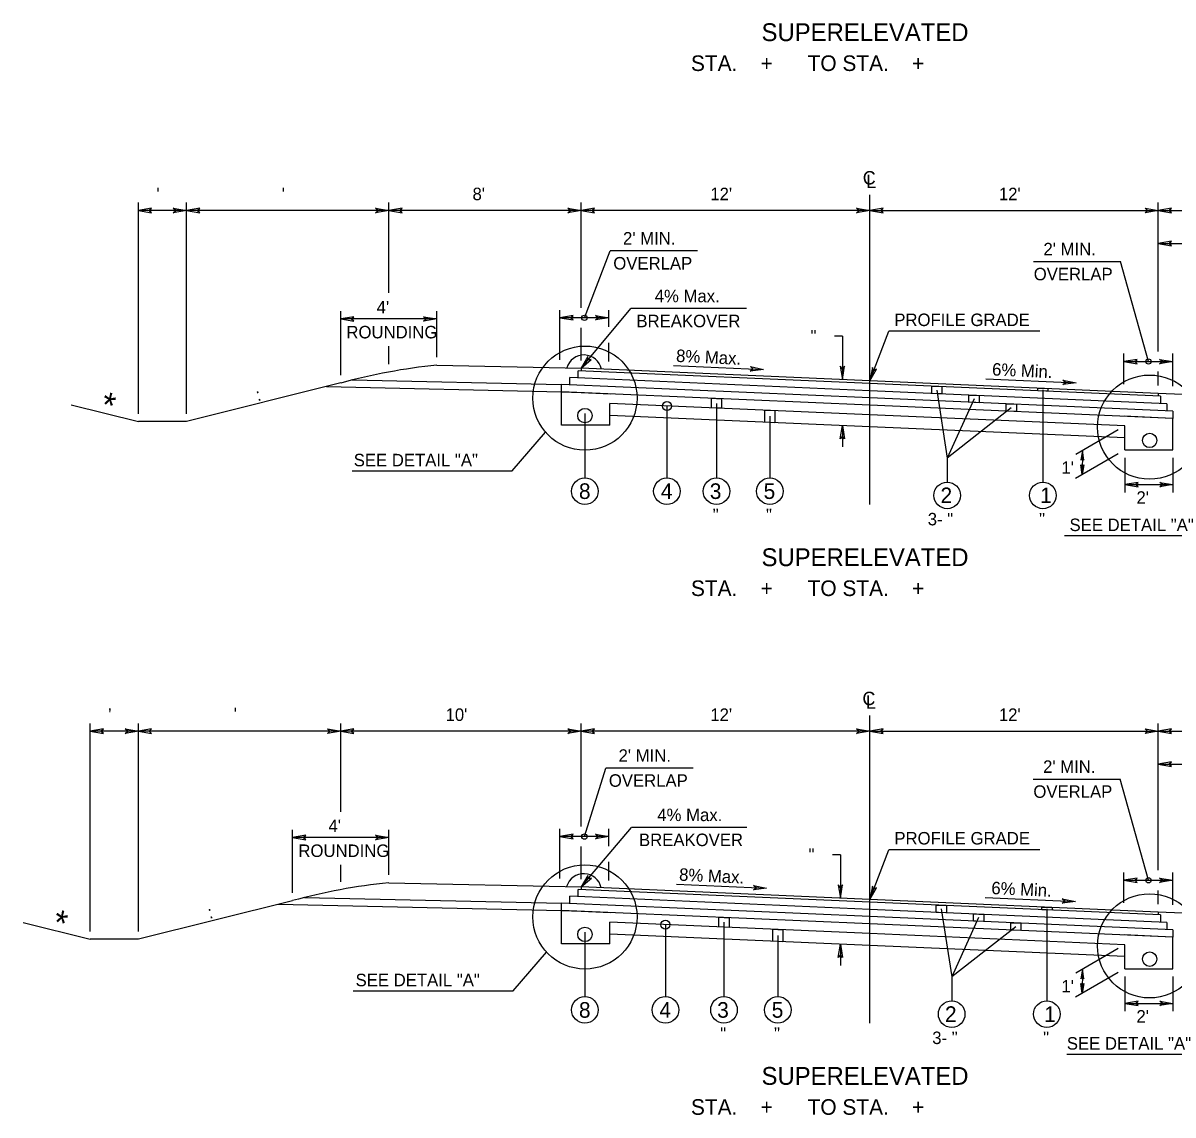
# Model space of a CAD drawing. Extents: x -540 to 1231, y -564 to 421.
# Drawn here: x 1027.6 to 1156.5, y 67.4 to 189.8 of the extents above; entities that cross this region are included whole.
import ezdxf

# ---------------------------------------------------------------- set-up
doc = ezdxf.new("R2010")
doc.units = 0
doc.layers.add('1', color=7, linetype='Continuous')
doc.layers.add('Des_ Drain_ Ftrs', color=7, linetype='Continuous')

msp = doc.modelspace()

# ---------------------------------------------------------------- linework, layer by layer
at = {"layer": '1'}
for p, q in [((1122.51, 135.84), (1122.51, 170.55)), ((1040.57, 146.01), (1040.57, 169.67)), ((1045.96, 168.79), (1040.57, 168.79)), ((1045.96, 146.01), (1045.96, 169.67)), ((1068.63, 168.79), (1045.96, 168.79)), ((1068.63, 159.57), (1068.63, 169.67)), ((1090.18, 168.79), (1068.63, 168.79)), ((1090.18, 157.88), (1090.18, 169.67)), ((1122.51, 168.79), (1090.18, 168.79)), ((1122.51, 168.79), (1154.84, 168.79)), ((1154.84, 152.98), (1154.84, 169.67)), ((1154.84, 168.79), (1176.39, 168.79)), ((1154.84, 165.08), (1182.58, 165.08)), ((1090.55, 156.75), (1093.44, 164.27)), ((1103.21, 164.27), (1093.44, 164.27)), ((1140.85, 163.06), (1150.61, 163.06)), ((1153.74, 151.86), (1150.61, 163.06)), ((1063.24, 150.33), (1063.24, 157.51)), ((1074.01, 152.34), (1074.01, 157.51)), ((1087.8, 152.04), (1087.8, 157.63)), ((1090.17, 151.1), (1095.73, 157.8)), ((1093.29, 155.74), (1093.29, 157.63)), ((1108.7, 157.8), (1095.73, 157.8)), ((1074.01, 156.63), (1063.24, 156.63)), ((1093.29, 156.75), (1087.8, 156.75)), ((1090.18, 151.98), (1090.18, 155.63)), ((1119.44, 154.71), (1118.56, 154.71)), ((1119.44, 154.71), (1119.44, 149.83)), ((1122.51, 149.69), (1124.65, 155.25)), ((1141.57, 155.25), (1124.65, 155.25)), ((1068.63, 151.56), (1068.63, 153.59)), ((1093.29, 151.85), (1093.29, 153.96)), ((1150.99, 149.33), (1150.99, 152.74)), ((1156.48, 149.09), (1156.48, 152.74)), ((1074.01, 151.46), (1090.17, 151.1)), ((1122.51, 149.39), (1089.83, 150.82)), ((1089.83, 150.01), (1089.83, 150.82)), ((1122.51, 149.69), (1090.17, 151.1)), ((1090.17, 151.1), (1090.17, 150.8)), ((1100.51, 151.41), (1110.62, 150.96)), ((1150.99, 151.86), (1156.48, 151.86)), ((1064.54, 149.79), (1087.94, 149.28)), ((1122.51, 148.58), (1088.91, 150.05)), ((1088.91, 149.24), (1088.91, 150.05)), ((1154.84, 148.28), (1122.51, 149.69)), ((1135.52, 149.9), (1145.64, 149.46)), ((1154.84, 149.16), (1154.84, 150.73)), ((1063.24, 149.45), (1045.96, 145.13)), ((1061.64, 149.05), (1087.99, 148.47)), ((1122.51, 147.77), (1087.99, 149.28)), ((1087.99, 148.47), (1087.99, 149.28)), ((1087.99, 144.72), (1087.99, 148.47)), ((1122.51, 146.97), (1087.99, 148.47)), ((1087.99, 148.47), (1090.17, 148.38)), ((1090.17, 148.38), (1093.47, 148.23)), ((1155.08, 147.97), (1122.51, 149.39)), ((1155.78, 147.13), (1122.51, 148.58)), ((1130.02, 148.66), (1131.19, 141.04)), ((1141.91, 148.67), (1141.91, 138.34)), ((1171, 147.57), (1154.84, 148.28)), ((1154.84, 148.28), (1154.84, 147.98)), ((1033.04, 147.01), (1040.57, 145.13)), ((1122.51, 145.89), (1093.38, 147.16)), ((1093.38, 144.72), (1093.38, 147.16)), ((1105.34, 147.15), (1105.34, 138.81)), ((1156.48, 146.29), (1122.51, 147.77)), ((1156.48, 145.48), (1122.51, 146.97)), ((1134.2, 147.68), (1131.19, 141.04)), ((1155.08, 147.97), (1155.08, 147.16)), ((1155.78, 147.13), (1155.78, 146.32)), ((1090.6, 146.02), (1090.6, 138.81)), ((1090.61, 146.02), (1090.61, 146.02)), ((1122.51, 144.54), (1093.38, 145.81)), ((1099.79, 146.86), (1099.79, 138.81)), ((1111.31, 145.72), (1111.31, 138.81)), ((1151.1, 144.64), (1122.51, 145.89)), ((1138.37, 146.66), (1131.19, 141.04)), ((1154.84, 145.55), (1151, 145.72)), ((1156.48, 146.29), (1156.48, 145.48)), ((1045.96, 145.13), (1040.57, 145.13)), ((1093.38, 144.72), (1087.99, 144.72)), ((1119.44, 144.67), (1119.44, 142.31)), ((1151.1, 143.29), (1122.51, 144.54)), ((1151.1, 141.94), (1151.1, 144.64)), ((1151.1, 144.64), (1151.1, 144.64)), ((1156.48, 145.48), (1154.84, 145.55)), ((1156.48, 141.94), (1156.48, 145.48)), ((1082.44, 139.61), (1086.18, 143.93)), ((1150.33, 144.2), (1145.58, 141.45)), ((1146.34, 141.89), (1146.32, 139.19)), ((1151.1, 141.94), (1156.48, 141.94)), ((1131.19, 141.04), (1131.19, 138.34)), ((1150.33, 141.5), (1145.56, 138.75)), ((1151.1, 141.06), (1151.1, 137.18)), ((1156.48, 141.06), (1156.48, 137.18)), ((1064.51, 139.61), (1082.44, 139.61)), ((1151.1, 138.06), (1156.48, 138.06)), ((1144.31, 132.34), (1163.09, 132.34)), ((1122.51, 77.69), (1122.51, 112.18)), ((1035.18, 87.98), (1035.18, 111.3)), ((1040.57, 87.98), (1040.57, 111.3)), ((1063.24, 101.39), (1063.24, 111.3)), ((1090.18, 99.74), (1090.18, 111.3)), ((1154.84, 94.84), (1154.84, 111.3)), ((1040.57, 110.42), (1035.18, 110.42)), ((1063.24, 110.42), (1040.57, 110.42)), ((1090.18, 110.42), (1063.24, 110.42)), ((1122.51, 110.42), (1090.18, 110.42)), ((1122.51, 110.42), (1154.84, 110.42)), ((1154.84, 110.42), (1181.78, 110.42)), ((1090.55, 98.61), (1092.95, 106.29)), ((1102.71, 106.29), (1092.95, 106.29)), ((1154.84, 106.72), (1188.21, 106.72)), ((1140.81, 105.05), (1150.57, 105.05)), ((1153.74, 93.71), (1150.57, 105.05)), ((1057.85, 92.3), (1057.85, 99.38)), ((1068.63, 94.31), (1068.63, 99.38)), ((1087.8, 93.89), (1087.8, 99.49)), ((1090.17, 92.96), (1095.81, 99.64)), ((1093.29, 97.54), (1093.29, 99.49)), ((1108.74, 99.64), (1095.81, 99.64)), ((1068.63, 98.5), (1057.85, 98.5)), ((1093.29, 98.61), (1087.8, 98.61)), ((1090.18, 93.84), (1090.18, 97.48)), ((1122.51, 91.55), (1124.66, 97.13)), ((1141.58, 97.13), (1124.66, 97.13)), ((1063.24, 93.53), (1063.24, 95.43)), ((1093.29, 93.7), (1093.29, 95.77)), ((1119.22, 96.57), (1118.34, 96.57)), ((1119.22, 96.57), (1119.22, 91.69)), ((1150.99, 91.18), (1150.99, 94.59)), ((1156.48, 90.94), (1156.48, 94.59)), ((1068.63, 93.43), (1090.17, 92.96)), ((1122.51, 91.55), (1090.17, 92.96)), ((1090.17, 92.96), (1090.17, 92.66)), ((1100.85, 93.26), (1110.96, 92.82)), ((1150.99, 93.71), (1156.48, 93.71)), ((1059.17, 91.77), (1087.99, 91.14)), ((1122.51, 90.44), (1088.91, 91.91)), ((1088.91, 91.1), (1088.91, 91.91)), ((1122.51, 91.25), (1089.83, 92.68)), ((1089.83, 91.87), (1089.83, 92.68)), ((1154.84, 90.14), (1122.51, 91.55)), ((1135.45, 91.76), (1145.56, 91.32)), ((1154.84, 91.02), (1154.84, 92.58)), ((1057.85, 91.42), (1040.57, 87.1)), ((1056.25, 91.02), (1087.99, 90.33)), ((1122.51, 89.63), (1087.99, 91.14)), ((1087.99, 90.33), (1087.99, 91.14)), ((1087.99, 86.57), (1087.99, 90.33)), ((1122.51, 88.82), (1087.99, 90.33)), ((1087.99, 90.33), (1090.17, 90.23)), ((1090.17, 90.23), (1093.47, 90.09)), ((1155.08, 89.83), (1122.51, 91.25)), ((1155.78, 88.99), (1122.51, 90.44)), ((1130.53, 90.5), (1131.69, 82.88)), ((1142.35, 90.52), (1142.35, 80.19)), ((1027.65, 88.98), (1035.18, 87.1)), ((1122.51, 87.74), (1093.38, 89.01)), ((1093.38, 86.57), (1093.38, 89.01)), ((1106.18, 89), (1106.18, 80.66)), ((1156.48, 88.15), (1122.51, 89.63)), ((1134.7, 89.52), (1131.69, 82.88)), ((1176.39, 89.19), (1154.84, 90.14)), ((1154.84, 90.14), (1154.84, 89.84)), ((1155.08, 89.83), (1155.08, 89.02)), ((1155.78, 88.99), (1155.78, 88.18)), ((1090.6, 87.88), (1090.6, 80.66)), ((1090.61, 87.88), (1090.61, 87.88)), ((1122.51, 86.39), (1093.38, 87.67)), ((1099.62, 88.74), (1099.62, 80.66)), ((1156.48, 87.34), (1122.51, 88.82)), ((1151.1, 86.49), (1122.51, 87.74)), ((1138.88, 88.5), (1131.69, 82.88)), ((1156.48, 88.15), (1156.48, 87.34)), ((1040.57, 87.1), (1035.18, 87.1)), ((1093.38, 86.57), (1087.99, 86.57)), ((1112.22, 87.53), (1112.22, 80.66)), ((1119.22, 86.54), (1119.22, 84.17)), ((1151.1, 85.15), (1122.51, 86.39)), ((1154.84, 87.41), (1151, 87.58)), ((1151.1, 83.8), (1151.1, 86.49)), ((1151.1, 86.49), (1151.1, 86.49)), ((1156.48, 87.34), (1154.84, 87.41)), ((1156.48, 83.8), (1156.48, 87.34)), ((1082.57, 81.32), (1086.31, 85.64)), ((1150.33, 86.05), (1145.58, 83.31)), ((1146.34, 83.75), (1146.32, 81.04)), ((1151.1, 83.8), (1156.48, 83.8)), ((1131.69, 82.88), (1131.69, 80.19)), ((1150.33, 83.36), (1145.56, 80.6)), ((1151.1, 82.92), (1151.1, 79.03)), ((1156.48, 82.92), (1156.48, 79.03)), ((1064.64, 81.32), (1082.57, 81.32)), ((1151.1, 79.91), (1156.48, 79.91)), ((1144.58, 74.22), (1163.37, 74.22))]:
    msp.add_line(p, q, dxfattribs=at)
for points in [[(1129.45, 149.09), (1130.6, 149.04), (1130.6, 148.23), (1129.45, 148.28)], [(1141.33, 148.87), (1142.48, 148.82), (1142.48, 148.52), (1141.33, 148.57)], [(1104.77, 147.74), (1105.92, 147.69), (1105.92, 146.61), (1104.77, 146.66)], [(1133.62, 148.1), (1134.77, 148.05), (1134.77, 147.24), (1133.62, 147.29)], [(1137.8, 147.11), (1138.95, 147.06), (1138.95, 146.25), (1137.8, 146.3)], [(1110.74, 146.4), (1111.88, 146.35), (1111.88, 145), (1110.74, 145.05)], [(1129.96, 90.92), (1131.1, 90.87), (1131.1, 90.06), (1129.96, 90.11)], [(1141.78, 90.71), (1142.93, 90.66), (1142.93, 90.36), (1141.78, 90.41)], [(1105.61, 89.56), (1106.75, 89.51), (1106.75, 88.43), (1105.61, 88.48)], [(1134.13, 89.93), (1135.28, 89.88), (1135.28, 89.07), (1134.13, 89.12)], [(1139.45, 88.89), (1139.45, 88.08), (1138.31, 88.13), (1138.31, 88.94)], [(1111.64, 88.22), (1112.79, 88.17), (1112.79, 86.82), (1111.64, 86.87)]]:
    msp.add_lwpolyline(points, close=True, dxfattribs=at)
for centre, radius in [((1090.55, 156.75), 0.3), ((1090.6, 147.75), 5.84), ((1153.74, 151.86), 0.3), ((1153.86, 144.5), 5.84), ((1099.79, 146.86), 0.5), ((1090.6, 145.79), 0.808), ((1153.87, 143.01), 0.808), ((1090.6, 137.32), 1.49), ((1099.79, 137.32), 1.49), ((1105.34, 137.32), 1.49), ((1111.31, 137.32), 1.49), ((1131.19, 136.85), 1.49), ((1141.91, 136.85), 1.49), ((1090.55, 98.61), 0.3), ((1090.6, 89.6), 5.84), ((1153.74, 93.71), 0.3), ((1153.86, 86.36), 5.84), ((1099.62, 88.74), 0.5), ((1090.6, 87.64), 0.808), ((1153.87, 84.87), 0.808), ((1090.6, 79.18), 1.49), ((1099.62, 79.18), 1.49), ((1106.18, 79.18), 1.49), ((1112.22, 79.18), 1.49), ((1131.69, 78.71), 1.49), ((1142.35, 78.71), 1.49)]:
    msp.add_circle(centre, radius, dxfattribs=at)
for centre, radius, start, end in [((1090.49, 150.59), 2, 12.002, 164.0279), ((1080.91, 84.62), 67.19, 95.8897, 105.2483), ((1090.47, 92.45), 2, 12.0711, 163.8991), ((1075.52, 26.6), 67.19, 95.8911, 105.2497)]:
    msp.add_arc(centre, radius, start, end, dxfattribs=at)
at = {"layer": 'Des_ Drain_ Ftrs'}
for points in [[(1040.57, 168.79), (1042.06, 168.54), (1041.76, 168.79), (1042.06, 169.03)], [(1045.96, 168.79), (1044.47, 168.54), (1044.77, 168.79), (1044.47, 169.03)], [(1045.96, 168.79), (1047.45, 168.54), (1047.15, 168.79), (1047.45, 169.03)], [(1068.63, 168.79), (1067.14, 168.54), (1067.43, 168.79), (1067.14, 169.03)], [(1068.63, 168.79), (1070.11, 168.54), (1069.82, 168.79), (1070.11, 169.03)], [(1090.18, 168.79), (1088.69, 168.54), (1088.99, 168.79), (1088.69, 169.03)], [(1090.18, 168.79), (1091.67, 168.54), (1091.37, 168.79), (1091.67, 169.03)], [(1122.51, 168.79), (1121.02, 168.54), (1121.31, 168.79), (1121.02, 169.03)], [(1122.51, 168.79), (1124, 168.54), (1123.7, 168.79), (1124, 169.03)], [(1154.84, 168.79), (1153.35, 168.54), (1153.64, 168.79), (1153.35, 169.03)], [(1154.84, 168.79), (1156.33, 168.54), (1156.03, 168.79), (1156.33, 169.03)], [(1154.84, 165.08), (1156.32, 164.84), (1156.03, 165.08), (1156.32, 165.33)], [(1063.24, 156.63), (1064.73, 156.39), (1064.43, 156.63), (1064.73, 156.88)], [(1074.01, 156.63), (1072.53, 156.39), (1072.82, 156.63), (1072.53, 156.88)], [(1087.8, 156.75), (1089.29, 156.51), (1089, 156.75), (1089.29, 157)], [(1093.29, 156.75), (1091.8, 156.51), (1092.1, 156.75), (1091.8, 157)], [(1090.17, 151.1), (1091.31, 152.09), (1090.93, 152.02), (1090.93, 152.41)], [(1150.99, 151.86), (1152.48, 151.61), (1152.19, 151.86), (1152.48, 152.1)], [(1156.48, 151.86), (1154.99, 151.61), (1155.29, 151.86), (1154.99, 152.1)], [(1110.62, 150.96), (1109.12, 150.78), (1109.43, 151.02), (1109.15, 151.28)], [(1119.44, 149.83), (1119.69, 151.32), (1119.44, 151.02), (1119.19, 151.32)], [(1122.51, 149.69), (1123.27, 150.99), (1122.93, 150.81), (1122.81, 151.17)], [(1145.64, 149.46), (1144.14, 149.28), (1144.44, 149.51), (1144.16, 149.77)], [(1119.44, 144.67), (1119.69, 143.19), (1119.44, 143.48), (1119.19, 143.19)], [(1146.34, 141.89), (1146.15, 140.81), (1146.33, 141.02), (1146.51, 140.81)], [(1146.32, 139.19), (1146.14, 140.27), (1146.32, 140.06), (1146.51, 140.27)], [(1151.1, 138.06), (1152.58, 137.81), (1152.29, 138.06), (1152.58, 138.31)], [(1156.48, 138.06), (1155, 137.81), (1155.29, 138.06), (1155, 138.31)], [(1035.18, 110.42), (1036.67, 110.17), (1036.38, 110.42), (1036.67, 110.67)], [(1040.57, 110.42), (1039.08, 110.17), (1039.38, 110.42), (1039.08, 110.67)], [(1040.57, 110.42), (1042.06, 110.17), (1041.77, 110.42), (1042.06, 110.67)], [(1063.24, 110.42), (1061.75, 110.17), (1062.04, 110.42), (1061.75, 110.67)], [(1063.24, 110.42), (1064.73, 110.17), (1064.43, 110.42), (1064.73, 110.67)], [(1090.18, 110.42), (1088.69, 110.17), (1088.99, 110.42), (1088.69, 110.67)], [(1090.18, 110.42), (1091.67, 110.17), (1091.37, 110.42), (1091.67, 110.67)], [(1122.51, 110.42), (1121.02, 110.17), (1121.31, 110.42), (1121.02, 110.67)], [(1122.51, 110.42), (1124, 110.17), (1123.7, 110.42), (1124, 110.67)], [(1154.84, 110.42), (1153.35, 110.17), (1153.64, 110.42), (1153.35, 110.67)], [(1154.84, 110.42), (1156.33, 110.17), (1156.03, 110.42), (1156.33, 110.67)], [(1154.84, 106.72), (1156.33, 106.47), (1156.03, 106.72), (1156.33, 106.97)], [(1057.85, 98.5), (1059.34, 98.25), (1059.04, 98.5), (1059.34, 98.75)], [(1068.63, 98.5), (1067.14, 98.25), (1067.43, 98.5), (1067.14, 98.75)], [(1087.8, 98.61), (1089.29, 98.36), (1089, 98.61), (1089.29, 98.86)], [(1093.29, 98.61), (1091.8, 98.36), (1092.1, 98.61), (1091.8, 98.86)], [(1090.17, 92.96), (1091.32, 93.94), (1090.94, 93.87), (1090.94, 94.26)], [(1110.96, 92.82), (1109.47, 92.63), (1109.77, 92.87), (1109.49, 93.13)], [(1119.22, 91.69), (1119.47, 93.18), (1119.22, 92.89), (1118.97, 93.18)], [(1122.51, 91.55), (1123.27, 92.85), (1122.93, 92.66), (1122.81, 93.03)], [(1150.99, 93.71), (1152.48, 93.46), (1152.19, 93.71), (1152.48, 93.96)], [(1156.48, 93.71), (1154.99, 93.46), (1155.29, 93.71), (1154.99, 93.96)], [(1145.56, 91.32), (1144.06, 91.14), (1144.37, 91.37), (1144.08, 91.63)], [(1119.22, 86.54), (1119.47, 85.05), (1119.22, 85.35), (1118.97, 85.05)], [(1146.34, 83.75), (1146.15, 82.66), (1146.33, 82.88), (1146.51, 82.66)], [(1146.32, 81.04), (1146.14, 82.13), (1146.32, 81.91), (1146.51, 82.12)], [(1151.1, 79.91), (1152.58, 79.67), (1152.29, 79.91), (1152.58, 80.16)], [(1156.48, 79.91), (1155, 79.67), (1155.29, 79.91), (1155, 80.16)]]:
    msp.add_lwpolyline(points, close=True, dxfattribs=at)

# ---------------------------------------------------------------- texts
at = {"layer": '1'}
for s, height, p in [('SUPERELEVATED', 2, (1110.39, 187.77)), ('STA.    +      TO STA.    +     ', 1.75, (1102.48, 184.42)), ("8'", 1.4, (1078.01, 169.94)), ("12'", 1.4, (1104.65, 169.94)), ("12'", 1.4, (1136.98, 169.94)), (" '", 1.4, (1042.07, 169.94)), ("  '", 1.4, (1055.6, 169.94)), ("2' MIN.", 1.4, (1094.87, 164.97)), ("2' MIN.", 1.4, (1141.97, 163.76)), ('OVERLAP', 1.4, (1093.78, 162.17)), ('OVERLAP', 1.4, (1140.88, 160.96)), ('4% Max.', 1.4, (1098.42, 158.5)), ("4'", 1.4, (1067.27, 157.25)), ('PROFILE GRADE', 1.4, (1125.26, 155.83)), ('BREAKOVER', 1.4, (1096.37, 155.7)), ('ROUNDING', 1.4, (1063.88, 154.45)), ('SEE DETAIL "A"', 1.4, (1064.7, 140.11)), ('8', 1.75, (1089.93, 136.45)), ('4', 1.75, (1099.11, 136.45)), ('3', 1.75, (1104.59, 136.45)), ('5', 1.75, (1110.62, 136.45)), ('2', 1.75, (1130.44, 135.98)), ('1', 1.75, (1141.61, 135.98)), ("2'", 1.4, (1152.39, 135.91)), (' "', 1.4, (1104.4, 133.96)), (' "', 1.4, (1110.37, 133.96)), ('3- "', 1.4, (1129.01, 133.49)), (' "', 1.4, (1140.96, 133.49)), ('SEE DETAIL "A"', 1.4, (1144.89, 132.85)), ('SUPERELEVATED', 2, (1110.39, 128.92)), ('STA.    +      TO STA.    +     ', 1.75, (1102.48, 125.57)), (" '", 1.4, (1036.68, 111.57)), ("  '", 1.4, (1050.21, 111.64)), ("10'", 1.4, (1074.99, 111.57)), ("12'", 1.4, (1104.65, 111.57)), ("12'", 1.4, (1136.98, 111.57)), ("2' MIN.", 1.4, (1094.37, 106.99)), ("2' MIN.", 1.4, (1141.93, 105.75)), ('OVERLAP', 1.4, (1093.28, 104.19)), ('OVERLAP', 1.4, (1140.84, 102.95)), ("4'", 1.4, (1061.88, 99.12)), ('4% Max.', 1.4, (1098.71, 100.34)), ('BREAKOVER', 1.4, (1096.66, 97.54)), ('PROFILE GRADE', 1.4, (1125.27, 97.72)), ('ROUNDING', 1.4, (1058.5, 96.32)), ('SEE DETAIL "A"', 1.4, (1064.91, 81.83)), ('8', 1.75, (1089.93, 78.3)), ('4', 1.75, (1098.95, 78.3)), ('3', 1.75, (1105.42, 78.3)), ('5', 1.75, (1111.53, 78.3)), ('2', 1.75, (1130.94, 77.83)), ('1', 1.75, (1142.05, 77.83)), ("2'", 1.4, (1152.39, 77.76)), (' "', 1.4, (1105.24, 75.82)), (' "', 1.4, (1111.27, 75.82)), ('3- "', 1.4, (1129.51, 75.35)), (' "', 1.4, (1141.41, 75.35)), ('SEE DETAIL "A"', 1.4, (1144.59, 74.73)), ('SUPERELEVATED', 2, (1110.39, 70.78)), ('STA.    +      TO STA.    +     ', 1.75, (1102.48, 67.42))]:
    msp.add_text(s, height=height, dxfattribs=at).set_placement(p)
for s, height, rotation, p in [('  "', 1.4, 0.1438, (1114.83, 154)), ('8% Max.', 1.4, 357.3762, (1100.79, 151.82)), ('6% Min.', 1.4, 357.3731, (1136.19, 150.3)), ('*', 2.8, 347.1521, (1036.2, 145.77)), (' : ', 1.4, 14.2282, (1053.42, 147.27)), ("1'", 1.4, 0.1438, (1143.99, 139.27)), ('  "', 1.4, 0.1438, (1114.61, 95.87)), ('8% Max.', 1.4, 357.3764, (1101.13, 93.67)), ('6% Min.', 1.4, 357.3731, (1136.11, 92.16)), ('*', 2.8, 347.1521, (1030.82, 87.74)), (' : ', 1.4, 14.2282, (1048.03, 89.25)), ("1'", 1.4, 0.1438, (1143.99, 81.13))]:
    msp.add_text(s, height=height, rotation=rotation, dxfattribs=at).set_placement(p)
at = {"layer": 'Des_ Drain_ Ftrs'}
for s, p in [('C', (1121.73, 171.7)), ('L', (1122.12, 171.3)), ('C', (1121.69, 113.34)), ('L', (1122.09, 112.94))]:
    msp.add_text(s, height=1.5, dxfattribs=at).set_placement(p)

doc.saveas('drawing.dxf')
